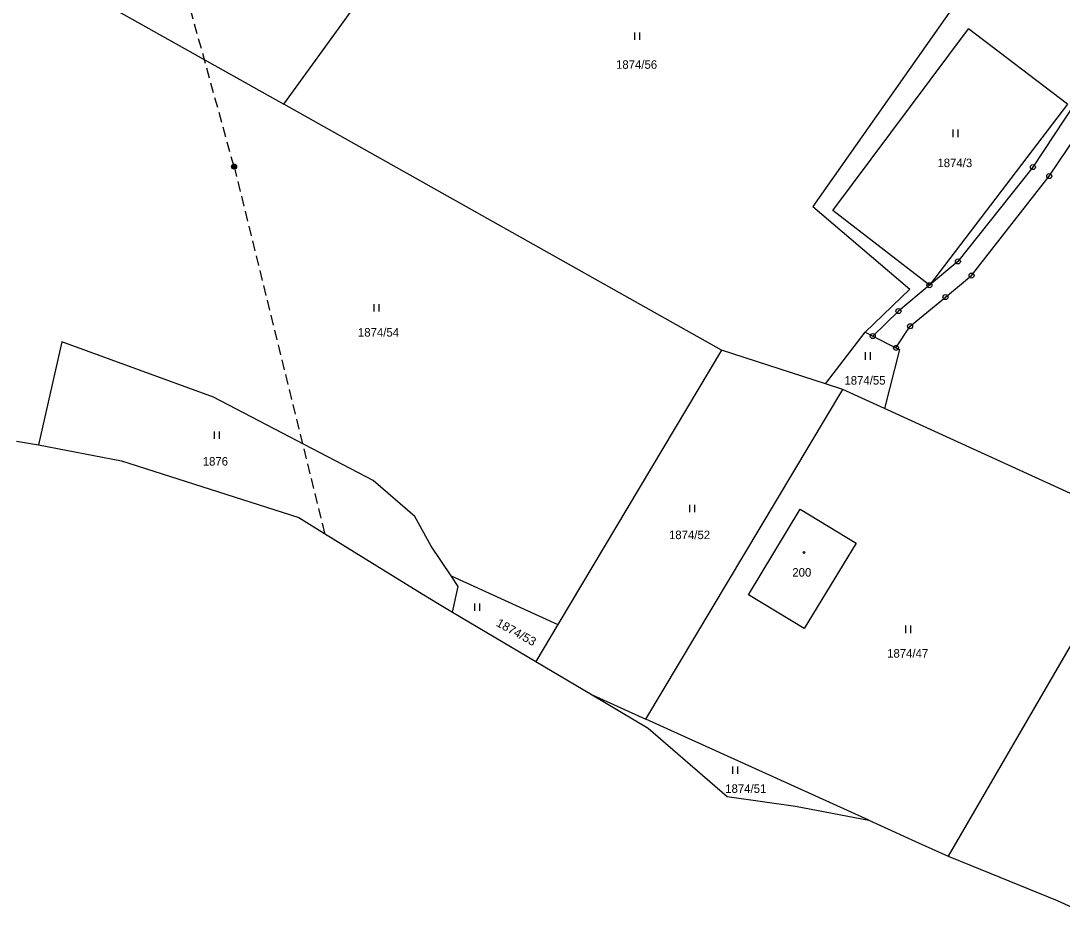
# Model space of a CAD drawing. Extents: x -820420 to -815896, y -1105820 to -1103643.
# Drawn here: x -818442.8 to -818234.8, y -1105556.8 to -1105375 of the extents above; entities that cross this region are included whole.
import ezdxf
from ezdxf.enums import TextEntityAlignment as Align

# ---------------------------------------------------------------- set-up
doc = ezdxf.new("R2010")
doc.units = 0
doc.header["$LTSCALE"] = 0.68
doc.linetypes.add('MEDIUM_DASHED', pattern=[4.5, 3, -1.5])
for name, color, linetype, lineweight in [('1', 7, 'Continuous', 25), ('3', 7, 'Continuous', 25), ('5', 7, 'Continuous', 25), ('6', 7, 'Continuous', 25), ('8', 7, 'Continuous', 25)]:
    doc.layers.add(name, color=color, linetype=linetype, lineweight=lineweight)
doc.layers.add('2', color=7, linetype='Continuous')

msp = doc.modelspace()

# ---------------------------------------------------------------- linework, layer by layer
at = {"layer": '1'}
for p, q in [((-818390.27, -1105391.68), (-818340.11, -1105322.2)), ((-818434.21, -1105366.96), (-818390.27, -1105391.68)), ((-818254.22, -1105368.94), (-818284.55, -1105412.09)), ((-818280.6, -1105412.93), (-818253.48, -1105376.62)), ((-818233.66, -1105391.63), (-818253.48, -1105376.62)), ((-818227.8, -1105384.72), (-818240.6, -1105404.25)), ((-818237.33, -1105406.05), (-818224.88, -1105387.41)), ((-818302.81, -1105440.87), (-818390.27, -1105391.68)), ((-818233.66, -1105391.63), (-818261.26, -1105427.85)), ((-818240.6, -1105404.25), (-818255.59, -1105423.11)), ((-818252.85, -1105425.92), (-818237.33, -1105406.05)), ((-818284.55, -1105412.09), (-818265.21, -1105428.66)), ((-818261.26, -1105427.85), (-818280.6, -1105412.93)), ((-818255.59, -1105423.11), (-818261.26, -1105427.85)), ((-818258.07, -1105430.23), (-818252.85, -1105425.92)), ((-818265.21, -1105428.66), (-818274.13, -1105437.24)), ((-818261.26, -1105427.85), (-818267.45, -1105433.02)), ((-818265.14, -1105436.06), (-818258.07, -1105430.23)), ((-818267.45, -1105433.02), (-818272.58, -1105438.03)), ((-818267.95, -1105440.38), (-818265.14, -1105436.06)), ((-818282.03, -1105447.57), (-818274.13, -1105437.24)), ((-818274.13, -1105437.24), (-818272.58, -1105438.03)), ((-818272.58, -1105438.03), (-818267.95, -1105440.38)), ((-818302.81, -1105440.87), (-818335.53, -1105495.68)), ((-818282.03, -1105447.57), (-818302.81, -1105440.87)), ((-818267.27, -1105440.73), (-818270.24, -1105452.5)), ((-818267.95, -1105440.38), (-818267.27, -1105440.73)), ((-818278.54, -1105448.7), (-818282.03, -1105447.57)), ((-818372.41, -1105466.9), (-818404.31, -1105450.27)), ((-818317.91, -1105514.63), (-818278.54, -1105448.7)), ((-818270.24, -1105452.5), (-818278.54, -1105448.7)), ((-818219.19, -1105475.87), (-818270.24, -1105452.5)), ((-818443.66, -1105459.04), (-818439.25, -1105459.77)), ((-818439.25, -1105459.77), (-818422.71, -1105462.96)), ((-818422.71, -1105462.96), (-818387.27, -1105474.29)), ((-818364.05, -1105474.13), (-818372.41, -1105466.9)), ((-818297.45, -1105489.75), (-818287.07, -1105472.64)), ((-818287.07, -1105472.64), (-818275.92, -1105479.46)), ((-818387.27, -1105474.29), (-818382.13, -1105477.47)), ((-818360.85, -1105480), (-818364.05, -1105474.13)), ((-818382.13, -1105477.47), (-818363.46, -1105489.04)), ((-818219.19, -1105475.87), (-818257.51, -1105542.04)), ((-818275.92, -1105479.46), (-818286.32, -1105496.52)), ((-818356.8, -1105485.98), (-818360.85, -1105480)), ((-818355.45, -1105488.08), (-818356.8, -1105485.98)), ((-818356.8, -1105485.98), (-818335.53, -1105495.68)), ((-818356.59, -1105493.21), (-818355.45, -1105488.08)), ((-818363.46, -1105489.04), (-818359.55, -1105491.46)), ((-818286.32, -1105496.52), (-818297.45, -1105489.75)), ((-818359.55, -1105491.46), (-818356.59, -1105493.21)), ((-818356.59, -1105493.21), (-818339.91, -1105503.07)), ((-818335.53, -1105495.68), (-818339.91, -1105503.07)), ((-818339.91, -1105503.07), (-818328.66, -1105509.74)), ((-818328.66, -1105509.74), (-818317.91, -1105514.63)), ((-818328.66, -1105509.74), (-818317.47, -1105516.44)), ((-818273.41, -1105534.83), (-818317.91, -1105514.63)), ((-818317.47, -1105516.44), (-818301.67, -1105530.07)), ((-818301.67, -1105530.07), (-818288.06, -1105531.99)), ((-818288.06, -1105531.99), (-818273.41, -1105534.83)), ((-818273.41, -1105534.83), (-818264.08, -1105539.06)), ((-818264.08, -1105539.06), (-818257.51, -1105542.04)), ((-818257.51, -1105542.04), (-818252.91, -1105543.9)), ((-818252.91, -1105543.9), (-818235.72, -1105550.86)), ((-818235.72, -1105550.86), (-818222.82, -1105556.81))]:
    msp.add_line(p, q, dxfattribs=at)
msp.add_lwpolyline([(-818404.31, -1105450.27), (-818434.59, -1105439.2), (-818439.25, -1105459.77)], dxfattribs=at)
at = {"layer": '3'}
for p, q in [((-818320.111, -1105378.8), (-818320.111, -1105377.3)), ((-818319.11, -1105378.8), (-818319.11, -1105377.3)), ((-818256.501, -1105398.24), (-818256.501, -1105396.74)), ((-818255.5, -1105398.24), (-818255.5, -1105396.74)), ((-818372.231, -1105433.12), (-818372.231, -1105431.62)), ((-818371.23, -1105433.12), (-818371.23, -1105431.62)), ((-818274.061, -1105442.75), (-818274.061, -1105441.25)), ((-818273.06, -1105442.75), (-818273.06, -1105441.25)), ((-818404.111, -1105458.6), (-818404.111, -1105457.1)), ((-818403.11, -1105458.6), (-818403.11, -1105457.1)), ((-818309.161, -1105473.25), (-818309.161, -1105471.75)), ((-818308.16, -1105473.25), (-818308.16, -1105471.75)), ((-818352.071, -1105492.98), (-818352.071, -1105491.48)), ((-818351.07, -1105492.98), (-818351.07, -1105491.48)), ((-818266.011, -1105497.4), (-818266.011, -1105495.9)), ((-818265.01, -1105497.4), (-818265.01, -1105495.9)), ((-818300.551, -1105525.56), (-818300.551, -1105524.06)), ((-818299.55, -1105525.56), (-818299.55, -1105524.06))]:
    msp.add_line(p, q, dxfattribs=at)
at = {"layer": '5'}
msp.add_circle((-818286.3268, -1105481.2892), 0.175, dxfattribs=at)
at = {"layer": '6', "linetype": 'MEDIUM_DASHED'}
for q in [(-818424.64, -1105315.94), (-818382.13, -1105477.47)]:
    msp.add_line((-818400.2, -1105404.14), q, dxfattribs=at)
at = {"layer": '6'}
for radius in [0.5, 0.4, 0.3, 0.2, 0.1]:
    msp.add_circle((-818400.2034, -1105404.1399), radius, dxfattribs=at)
at = {"layer": '8'}
for centre, radius in [((-818240.6, -1105404.2499), 0.5), ((-818240.6, -1105404.2499), 0.0303), ((-818237.33, -1105406.0499), 0.5), ((-818237.33, -1105406.0499), 0.0303), ((-818255.59, -1105423.1099), 0.5), ((-818255.59, -1105423.1099), 0.0303), ((-818252.85, -1105425.9199), 0.5), ((-818261.26, -1105427.8499), 0.5), ((-818252.85, -1105425.9199), 0.0303), ((-818261.26, -1105427.8499), 0.0303), ((-818258.07, -1105430.2299), 0.5), ((-818258.07, -1105430.2299), 0.0303), ((-818267.45, -1105433.0199), 0.5), ((-818267.45, -1105433.0199), 0.0303), ((-818265.14, -1105436.0599), 0.5), ((-818265.14, -1105436.0599), 0.0303), ((-818272.58, -1105438.0299), 0.5), ((-818272.58, -1105438.0299), 0.0303), ((-818267.95, -1105440.3799), 0.5), ((-818267.95, -1105440.3799), 0.0303)]:
    msp.add_circle(centre, radius, dxfattribs=at)

# ---------------------------------------------------------------- texts
at = {"layer": '2'}
for s, p in [('1874/56', (-818319.779, -1105384.585)), ('1874/3', (-818256.2, -1105404.245)), ('1874/54', (-818371.339, -1105438.135)), ('1874/55', (-818274.149, -1105447.735)), ('1876', (-818403.93, -1105463.915)), ('1874/52', (-818309.199, -1105478.625)), ('200', (-818286.769, -1105486.125)), ('1874/47', (-818265.619, -1105502.315)), ('1874/51', (-818297.959, -1105529.355))]:
    msp.add_text(s, height=1.7, dxfattribs=at).set_placement(p, align=Align.CENTER)
at = {"layer": '2', "width": 1.05}
msp.add_text('1874/53', height=1.7, rotation=331, dxfattribs=at).set_placement((-818344.2161, -1105497.9674), align=Align.CENTER)

doc.saveas('drawing.dxf')
